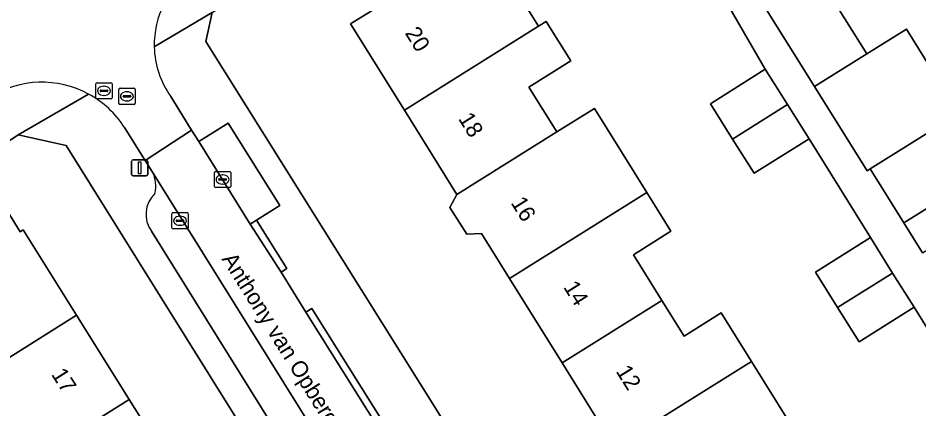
# Model space of a CAD drawing. Extents: x 159352 to 160617, y 385888 to 387323.
# Drawn here: x 159733.6 to 159789.2, y 386186.4 to 386210.5 of the extents above; entities that cross this region are included whole.
import ezdxf

# ---------------------------------------------------------------- set-up
doc = ezdxf.new("R2010")
doc.units = 0
for name, color, linetype in [('IMGEO_Erf', 7, 'Continuous'), ('IMGEO_Groenvoorziening', 7, 'Continuous'), ('IMGEO_Kolk', 7, 'Continuous'), ('IMGEO_Lichtmast', 7, 'Continuous'), ('IMGEO_Openbare_ruimte_label', 7, 'Continuous'), ('IMGEO_Pand', 7, 'Continuous'), ('IMGEO_Pand_nummerreeks', 7, 'Continuous'), ('IMGEO_Parkeervlak_open', 7, 'Continuous'), ('IMGEO_Rijbaan_lokaal_open', 7, 'Continuous'), ('IMGEO_Rioolput', 7, 'Continuous'), ('IMGEO_Voetpad_open', 7, 'Continuous')]:
    doc.layers.add(name, color=color, linetype=linetype)

msp = doc.modelspace()

# ---------------------------------------------------------------- linework, layer by layer
at = {"layer": 'IMGEO_Erf'}
for points in [[(159793.173, 386240.363), (159775.161, 386229.041), (159770.299, 386226.046), (159770.825, 386225.212), (159773.906, 386227.157), (159775.527, 386228.18), (159780.971, 386219.554), (159779.346, 386218.538), (159780.625, 386216.512), (159777.544, 386214.567), (159779.607, 386211.324), (159782.839, 386213.345), (159786.004, 386208.282), (159788.448, 386209.81), (159791.685, 386204.605), (159786.216, 386201.187), (159788.288, 386197.868), (159790.961, 386199.537)], [(159762.567, 386215.059), (159765.736, 386209.983), (159766.213, 386210.282), (159767.73, 386207.852), (159765.143, 386206.231), (159766.868, 386203.467), (159769.19, 386204.918), (159772.432, 386199.725), (159773.913, 386197.353), (159771.593, 386195.898), (159773.352, 386193.08), (159774.728, 386190.876), (159777.016, 386192.312), (159778.884, 386189.318), (159782.126, 386184.126), (159785.367, 386178.932), (159788.609, 386173.739), (159791.851, 386168.545)], [(159792.71, 386186.564), (159788.923, 386192.666), (159785.534, 386190.53), (159784.203, 386192.643), (159782.835, 386194.814), (159786.223, 386196.949), (159782.436, 386203.051), (159779.047, 386200.915), (159777.715, 386203.028), (159776.348, 386205.199), (159779.736, 386207.334), (159776.037, 386213.7)], [(159770.437, 386184.037), (159767.194, 386189.229), (159763.95, 386194.422), (159762.216, 386197.197), (159761.308, 386197.16), (159760.274, 386198.814), (159760.706, 386199.614), (159757.464, 386204.805), (159754.14, 386210.126), (159757.508, 386212.23)], [(159745.591, 386210.827), (159745.213, 386209.036), (159781.317, 386151.464)], [(159765.891, 386141.835), (159772.114, 386145.744), (159736.577, 386202.635), (159733.614, 386203.294), (159731.071, 386201.577), (159714.574, 386191.233), (159711.363, 386189.221), (159716.018, 386181.79), (159719.157, 386183.716), (159720.439, 386181.626), (159721.721, 386179.537), (159718.582, 386177.611), (159722.427, 386170.969), (159725.189, 386172.667), (159726.296, 386170.867), (159729.487, 386165.678), (159732.679, 386160.486), (159735.84, 386155.345), (159733.077, 386153.646), (159739.919, 386142.917)], [(159732.069, 386199.987), (159733.747, 386197.316), (159733.919, 386197.424), (159737.217, 386192.175), (159740.48, 386186.981), (159743.721, 386181.822), (159746.963, 386176.663), (159750.204, 386171.504), (159753.445, 386166.345), (159756.687, 386161.185), (159759.928, 386156.026), (159763.17, 386150.866), (159766.492, 386145.578)]]:
    msp.add_lwpolyline(points, dxfattribs=at)
at = {"layer": 'IMGEO_Groenvoorziening'}
msp.add_lwpolyline([(159744.763, 386202.873), (159747.945, 386197.778), (159748.327, 386198.031), (159749.779, 386198.928), (159746.587, 386204.015)], close=True, dxfattribs=at)
at = {"layer": 'IMGEO_Kolk'}
for p, q in [((159745.737, 386200.11), (159745.737, 386200.962)), ((159745.812, 386201.036), (159746.664, 386201.036)), ((159746.225, 386200.816), (159746.25, 386200.816)), ((159746.738, 386200.962), (159746.738, 386200.11)), ((159745.996, 386200.53), (159745.996, 386200.542)), ((159746.434, 386200.493), (159746.036, 386200.493)), ((159746.039, 386200.579), (159746.437, 386200.579)), ((159746.248, 386200.256), (159746.223, 386200.256)), ((159746.48, 386200.542), (159746.48, 386200.53)), ((159746.664, 386200.036), (159745.812, 386200.036)), ((159743.109, 386197.564), (159743.109, 386198.416)), ((159743.184, 386198.49), (159744.036, 386198.49)), ((159743.368, 386197.984), (159743.368, 386197.996)), ((159743.411, 386198.033), (159743.809, 386198.033)), ((159743.597, 386198.27), (159743.622, 386198.27)), ((159743.852, 386197.996), (159743.852, 386197.984)), ((159744.11, 386198.416), (159744.11, 386197.564)), ((159744.036, 386197.49), (159743.184, 386197.49)), ((159743.806, 386197.947), (159743.408, 386197.947)), ((159743.62, 386197.71), (159743.595, 386197.71))]:
    msp.add_line(p, q, dxfattribs=at)
for points in [[(159745.737, 386200.11), (159745.737, 386200.962)], [(159745.812, 386201.036), (159746.664, 386201.036)], [(159746.738, 386200.962), (159746.738, 386200.11)], [(159746.664, 386200.036), (159745.812, 386200.036)], [(159743.109, 386197.564), (159743.109, 386198.416)], [(159743.184, 386198.49), (159744.036, 386198.49)], [(159744.11, 386198.416), (159744.11, 386197.564)], [(159744.036, 386197.49), (159743.184, 386197.49)]]:
    msp.add_lwpolyline(points, dxfattribs=at)
for centre, radius, start, end in [((159745.814, 386200.96), 0.0765, 91.552, 178.448), ((159745.814, 386200.96), 0.0765, 91.552, 178.448), ((159746.662, 386200.96), 0.0765, 1.552, 88.448), ((159746.662, 386200.96), 0.0765, 1.552, 88.448), ((159746.036, 386200.539), 0.0403, 85.8775, 175.7526), ((159746.033, 386200.529), 0.0366, 178.938, 274.7102), ((159746.437, 386200.536), 0.043, 264.8664, 352.4533), ((159746.441, 386200.541), 0.0386, 1.7309, 96.639), ((159745.814, 386200.112), 0.0765, 181.552, 268.448), ((159745.814, 386200.112), 0.0765, 181.552, 268.448), ((159746.662, 386200.112), 0.0765, 271.552, 358.448), ((159746.662, 386200.112), 0.0765, 271.552, 358.448), ((159743.186, 386198.414), 0.0765, 91.552, 178.448), ((159743.186, 386198.414), 0.0765, 91.552, 178.448), ((159743.408, 386197.993), 0.0403, 85.8775, 175.7526), ((159743.405, 386197.983), 0.0366, 178.938, 274.7102), ((159743.809, 386197.99), 0.043, 264.8664, 352.4533), ((159743.813, 386197.995), 0.0386, 1.7309, 96.639), ((159744.034, 386198.414), 0.0765, 1.552, 88.448), ((159744.034, 386198.414), 0.0765, 1.552, 88.448), ((159743.186, 386197.566), 0.0765, 181.552, 268.448), ((159743.186, 386197.566), 0.0765, 181.552, 268.448), ((159744.034, 386197.566), 0.0765, 271.552, 358.448), ((159744.034, 386197.566), 0.0765, 271.552, 358.448)]:
    msp.add_arc(centre, radius, start, end, dxfattribs=at)
for centre, major_axis, ratio, start_param, end_param in [((159746.224, 386200.536), (-0.387, 0.002), 0.722429, 4.712389, 7.853982), ((159746.249, 386200.536), (-0.39, 0.002), 0.717154, 1.570796, 4.712389), ((159743.596, 386197.99), (-0.387, 0.002), 0.722429, 4.712389, 7.853982), ((159743.621, 386197.99), (-0.39, 0.002), 0.717154, 1.570796, 4.712389)]:
    msp.add_ellipse(centre, major_axis=major_axis, ratio=ratio, start_param=start_param, end_param=end_param, dxfattribs=at)
at = {"layer": 'IMGEO_Lichtmast'}
for p, q in [((159740.626, 386200.851), (159740.626, 386201.651)), ((159740.626, 386201.651), (159740.626, 386200.851)), ((159740.726, 386201.751), (159741.516, 386201.751)), ((159741.516, 386201.751), (159740.726, 386201.751)), ((159741.616, 386201.651), (159741.616, 386200.851)), ((159741.616, 386200.851), (159741.616, 386201.651)), ((159741.516, 386200.751), (159740.726, 386200.751)), ((159740.726, 386200.751), (159741.516, 386200.751))]:
    msp.add_line(p, q, dxfattribs=at)
msp.add_lwpolyline([(159741.046, 386201.626), (159741.196, 386201.626), (159741.196, 386200.876), (159741.046, 386200.876), (159741.046, 386201.626)], dxfattribs=at)
for centre, start, end in [((159740.726, 386201.651), 90, 180), ((159740.726, 386201.651), 90, 180), ((159741.516, 386201.651), 0, 90), ((159741.516, 386201.651), 360, 90), ((159740.726, 386200.851), 180, 270), ((159740.726, 386200.851), 180, 270), ((159741.516, 386200.851), 270, 0), ((159741.516, 386200.851), 270, 0)]:
    msp.add_arc(centre, 0.1, start, end, dxfattribs=at)
at = {"layer": 'IMGEO_Pand'}
for points in [[(159762.567, 386215.059), (159761.735, 386214.54), (159759.813, 386217.62), (159755.734, 386215.072), (159757.508, 386212.23), (159754.14, 386210.126), (159757.464, 386204.805), (159765.736, 386209.983)], [(159786.004, 386208.282), (159782.839, 386213.345), (159779.607, 386211.324), (159782.771, 386206.262)], [(159767.73, 386207.852), (159766.213, 386210.282), (159765.736, 386209.983), (159757.464, 386204.805), (159760.706, 386199.614), (159766.868, 386203.467), (159765.143, 386206.231)], [(159786.004, 386208.282), (159782.771, 386206.262), (159786.02, 386201.064), (159786.216, 386201.187), (159791.685, 386204.605), (159788.448, 386209.81)], [(159779.736, 386207.334), (159776.348, 386205.199), (159777.715, 386203.028), (159781.112, 386205.152)], [(159763.95, 386194.422), (159772.432, 386199.725), (159769.19, 386204.918), (159766.868, 386203.467), (159760.706, 386199.614), (159760.274, 386198.814), (159761.308, 386197.16), (159762.216, 386197.197)], [(159779.047, 386200.915), (159782.436, 386203.051), (159781.112, 386205.152), (159777.715, 386203.028)], [(159737.217, 386192.175), (159733.919, 386197.424), (159733.747, 386197.316), (159732.069, 386199.987), (159724.564, 386195.272), (159726.351, 386192.428), (159725.32, 386191.78), (159728.511, 386186.701)], [(159763.95, 386194.422), (159767.194, 386189.229), (159773.352, 386193.08), (159771.593, 386195.898), (159773.913, 386197.353), (159772.432, 386199.725)], [(159792.117, 386197.686), (159790.961, 386199.537), (159788.288, 386197.868), (159789.444, 386196.017)], [(159786.223, 386196.949), (159782.835, 386194.814), (159784.203, 386192.643), (159787.599, 386194.766)], [(159785.534, 386190.53), (159788.923, 386192.666), (159787.599, 386194.766), (159784.203, 386192.643)], [(159767.194, 386189.229), (159770.437, 386184.037), (159778.884, 386189.318), (159777.016, 386192.312), (159774.728, 386190.876), (159773.352, 386193.08)], [(159728.511, 386186.701), (159729.948, 386184.414), (159732.499, 386186.019), (159734.325, 386183.112), (159740.48, 386186.981), (159737.217, 386192.175)], [(159782.126, 386184.126), (159778.884, 386189.318), (159770.437, 386184.037), (159771.731, 386181.965), (159771.059, 386181.545), (159772.507, 386179.227), (159773.454, 386179.207), (159773.68, 386178.845)], [(159734.325, 386183.112), (159737.567, 386177.953), (159743.721, 386181.822), (159740.48, 386186.981)]]:
    msp.add_lwpolyline(points, close=True, dxfattribs=at)
at = {"layer": 'IMGEO_Parkeervlak_open'}
for points in [[(159788.47, 386126.403), (159741.92, 386200.989)], [(159741.852, 386197.34), (159771.528, 386149.758)]]:
    msp.add_lwpolyline(points, dxfattribs=at)
for centre, radius, start, end in [((159740.16, 386200.144), 1.953, 346.1966, 25.6485), ((159743.299, 386198.392), 1.789, 134.0204, 216.0062)]:
    msp.add_arc(centre, radius, start, end, dxfattribs=at)
at = {"layer": 'IMGEO_Rijbaan_lokaal_open'}
msp.add_lwpolyline([(159740.185, 386203.732), (159741.463, 386201.705), (159744.31, 386203.581), (159743.038, 386205.645)], dxfattribs=at)
msp.add_lwpolyline([(159747.945, 386197.778), (159744.763, 386202.873), (159744.31, 386203.581), (159741.463, 386201.705), (159741.92, 386200.989), (159788.47, 386126.403), (159788.572, 386126.24), (159791.629, 386128.131), (159784.367, 386139.74), (159782.945, 386141.957), (159781.25, 386144.716), (159776.428, 386152.399), (159773.531, 386157.033), (159771.654, 386160.035), (159768.984, 386164.269), (159764.702, 386171.113), (159762.065, 386175.311), (159758.308, 386181.306), (159755.937, 386185.075), (159751.368, 386192.352), (159749.848, 386194.818)], close=True, dxfattribs=at)
for centre, radius, start, end in [((159747.548, 386208.838), 5.529, 124.6749, 181.2364), ((159747.54, 386208.84), 5.521, 181.254, 215.3585), ((159735.079, 386200.478), 6.055, 61.5093, 121.9861), ((159735.083, 386200.484), 6.048, 32.4856, 61.5232)]:
    msp.add_arc(centre, radius, start, end, dxfattribs=at)
at = {"layer": 'IMGEO_Rioolput'}
for p, q in [((159738.415, 386205.576), (159738.415, 386206.428)), ((159738.49, 386206.502), (159739.342, 386206.502)), ((159739.416, 386206.428), (159739.416, 386205.576)), ((159738.674, 386205.996), (159738.674, 386206.008)), ((159739.112, 386205.959), (159738.714, 386205.959)), ((159738.717, 386206.045), (159739.115, 386206.045)), ((159738.903, 386206.282), (159738.928, 386206.282)), ((159739.158, 386206.008), (159739.158, 386205.996)), ((159739.833, 386205.235), (159739.833, 386206.087)), ((159739.908, 386206.161), (159740.76, 386206.161)), ((159740.321, 386205.941), (159740.346, 386205.941)), ((159740.834, 386206.087), (159740.834, 386205.235)), ((159739.342, 386205.502), (159738.49, 386205.502)), ((159738.926, 386205.722), (159738.901, 386205.722)), ((159740.092, 386205.655), (159740.092, 386205.667)), ((159740.53, 386205.618), (159740.132, 386205.618)), ((159740.135, 386205.704), (159740.533, 386205.704)), ((159740.344, 386205.381), (159740.319, 386205.381)), ((159740.576, 386205.667), (159740.576, 386205.655)), ((159740.76, 386205.161), (159739.908, 386205.161))]:
    msp.add_line(p, q, dxfattribs=at)
for points in [[(159738.415, 386205.576), (159738.415, 386206.428)], [(159738.49, 386206.502), (159739.342, 386206.502)], [(159739.416, 386206.428), (159739.416, 386205.576)], [(159739.833, 386205.235), (159739.833, 386206.087)], [(159739.908, 386206.161), (159740.76, 386206.161)], [(159740.834, 386206.087), (159740.834, 386205.235)], [(159739.342, 386205.502), (159738.49, 386205.502)], [(159740.76, 386205.161), (159739.908, 386205.161)]]:
    msp.add_lwpolyline(points, dxfattribs=at)
for centre, radius, start, end in [((159738.492, 386206.426), 0.0765, 91.552, 178.448), ((159738.492, 386206.426), 0.0765, 91.552, 178.448), ((159739.34, 386206.426), 0.0765, 1.552, 88.448), ((159739.34, 386206.426), 0.0765, 1.552, 88.448), ((159738.714, 386206.005), 0.0403, 85.8775, 175.7526), ((159738.711, 386205.995), 0.0366, 178.938, 274.7102), ((159739.115, 386206.002), 0.043, 264.8664, 352.4533), ((159739.119, 386206.007), 0.0386, 1.7309, 96.639), ((159739.91, 386206.085), 0.0765, 91.552, 178.448), ((159739.91, 386206.085), 0.0765, 91.552, 178.448), ((159740.758, 386206.085), 0.0765, 1.552, 88.448), ((159740.758, 386206.085), 0.0765, 1.552, 88.448), ((159738.492, 386205.578), 0.0765, 181.552, 268.448), ((159738.492, 386205.578), 0.0765, 181.552, 268.448), ((159739.34, 386205.578), 0.0765, 271.552, 358.448), ((159739.34, 386205.578), 0.0765, 271.552, 358.448), ((159739.91, 386205.237), 0.0765, 181.552, 268.448), ((159739.91, 386205.237), 0.0765, 181.552, 268.448), ((159740.132, 386205.664), 0.0403, 85.8775, 175.7526), ((159740.129, 386205.654), 0.0366, 178.938, 274.7102), ((159740.533, 386205.661), 0.043, 264.8664, 352.4533), ((159740.537, 386205.666), 0.0386, 1.7309, 96.639), ((159740.758, 386205.237), 0.0765, 271.552, 358.448), ((159740.758, 386205.237), 0.0765, 271.552, 358.448)]:
    msp.add_arc(centre, radius, start, end, dxfattribs=at)
for centre, major_axis, ratio, start_param, end_param in [((159738.902, 386206.002), (-0.387, 0.002), 0.722429, 4.712389, 7.853982), ((159738.927, 386206.002), (-0.39, 0.002), 0.717154, 1.570796, 4.712389), ((159740.32, 386205.661), (-0.387, 0.002), 0.722429, 4.712389, 7.853982), ((159740.345, 386205.661), (-0.39, 0.002), 0.717154, 1.570796, 4.712389)]:
    msp.add_ellipse(centre, major_axis=major_axis, ratio=ratio, start_param=start_param, end_param=end_param, dxfattribs=at)
at = {"layer": 'IMGEO_Voetpad_open'}
for points in [[(159789.444, 386196.017), (159788.288, 386197.868), (159786.216, 386201.187), (159786.02, 386201.064), (159782.771, 386206.262), (159779.607, 386211.324), (159777.544, 386214.567), (159776.257, 386216.607), (159770.825, 386225.212), (159770.299, 386226.046), (159768.892, 386225.18), (159769.393, 386224.367), (159774.815, 386215.663), (159776.037, 386213.7), (159779.736, 386207.334), (159781.112, 386205.152), (159782.436, 386203.051), (159786.223, 386196.949), (159787.599, 386194.766), (159788.923, 386192.666), (159792.71, 386186.564)], [(159742.021, 386208.719), (159745.591, 386210.827), (159768.892, 386225.18)], [(159745.213, 386209.036), (159745.591, 386210.827), (159742.021, 386208.719)], [(159794.601, 386124.356), (159797.259, 386126.043), (159782.471, 386149.624), (159781.317, 386151.464), (159745.213, 386209.036)], [(159731.071, 386201.577), (159733.614, 386203.294), (159737.967, 386205.8)], [(159737.967, 386205.8), (159733.614, 386203.294), (159736.577, 386202.635), (159772.114, 386145.744), (159773.047, 386144.253), (159779.029, 386134.648), (159782.701, 386128.77), (159787.187, 386121.946), (159786.376, 386119.338), (159790.69, 386121.981)], [(159743.038, 386205.645), (159744.31, 386203.581), (159744.763, 386202.873), (159746.587, 386204.015), (159749.779, 386198.928), (159748.327, 386198.031), (159750.208, 386195.041), (159749.848, 386194.818), (159751.368, 386192.352), (159751.738, 386192.588), (159756.306, 386185.316)], [(159741.463, 386201.705), (159740.185, 386203.732)], [(159741.92, 386200.989), (159741.463, 386201.705)], [(159785.129, 386127.992), (159773.657, 386146.357), (159773.281, 386146.127), (159771.159, 386149.531), (159771.528, 386149.758), (159741.852, 386197.34)]]:
    msp.add_lwpolyline(points, dxfattribs=at)
for points in [[(159749.848, 386194.818), (159750.208, 386195.041), (159748.327, 386198.031), (159747.945, 386197.778)], [(159751.738, 386192.588), (159751.368, 386192.352), (159755.937, 386185.075), (159756.306, 386185.316)]]:
    msp.add_lwpolyline(points, close=True, dxfattribs=at)
for centre, radius, start, end in [((159747.548, 386208.838), 5.529, 124.6749, 181.2364), ((159747.54, 386208.84), 5.521, 181.254, 215.3585), ((159735.079, 386200.478), 6.055, 61.5093, 121.9861), ((159735.083, 386200.484), 6.048, 32.4856, 61.5232), ((159740.16, 386200.144), 1.953, 346.1966, 25.6485), ((159743.299, 386198.392), 1.789, 134.0204, 216.0062)]:
    msp.add_arc(centre, radius, start, end, dxfattribs=at)

# ---------------------------------------------------------------- texts
at = {"layer": 'IMGEO_Openbare_ruimte_label'}
msp.add_text('Anthony van Opbergenstraat', height=1, rotation=302.1329, dxfattribs=at).set_placement((159746.16, 386195.632))
at = {"layer": 'IMGEO_Pand_nummerreeks'}
for s, rotation, p in [('20', 301.9914, (159757.464, 386209.562)), ('18', 301.9914, (159760.757, 386204.29)), ('16', 301.9914, (159764, 386199.098)), ('14', 301.9914, (159767.244, 386193.904)), ('17', 302.1397, (159735.636, 386188.525)), ('12', 301.9914, (159770.488, 386188.712))]:
    msp.add_text(s, height=1, rotation=rotation, dxfattribs=at).set_placement(p)

doc.saveas('drawing.dxf')
